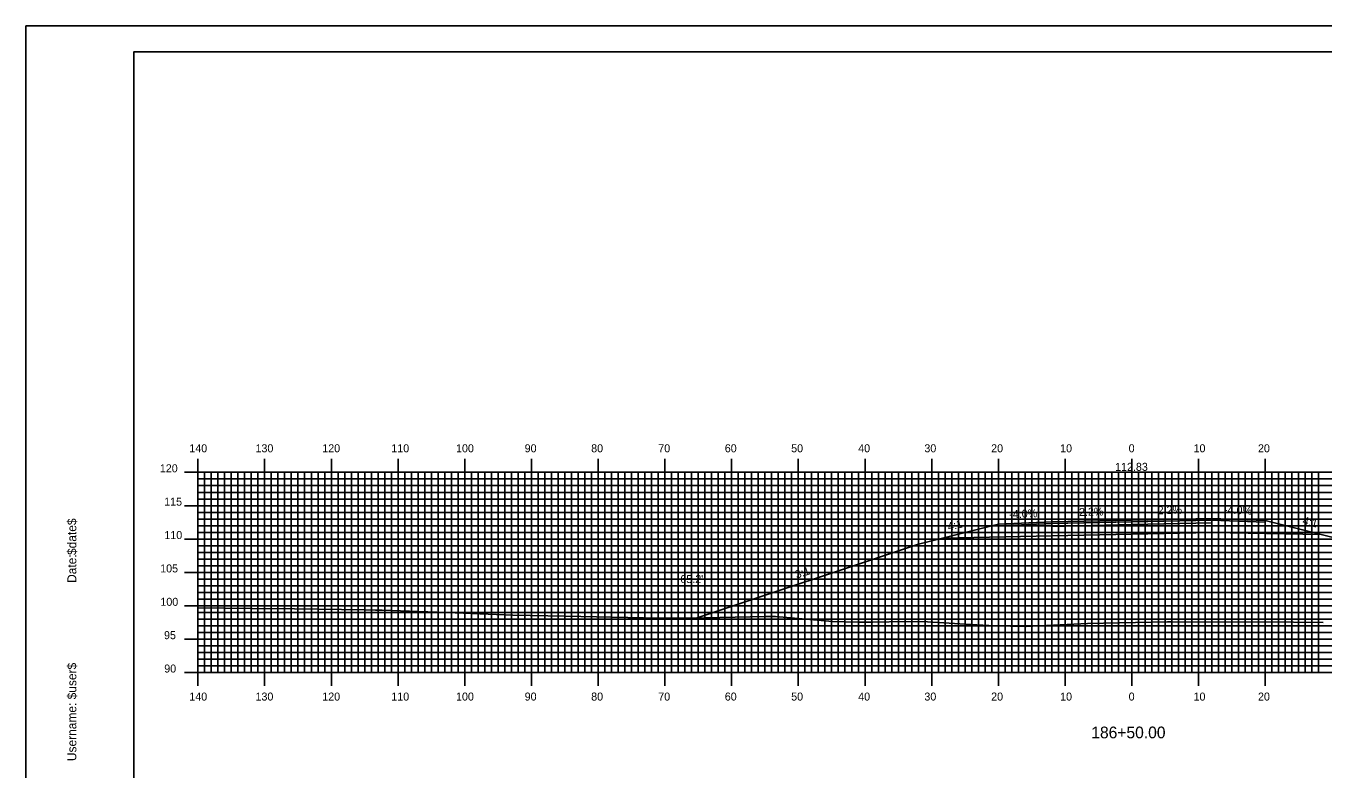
# Model space of a CAD drawing. Extents: x 1787369 to 1787713, y 442591 to 442811.
# Drawn here: x 1787369.3 to 1787563.8, y 442699.2 to 442810.5 of the extents above; entities that cross this region are included whole.
import ezdxf

# ---------------------------------------------------------------- set-up
doc = ezdxf.new("R2010")
doc.units = 0
for name, color, linetype in [('ANNOTATION', 7, 'Continuous'), ('BORDER', 7, 'Continuous'), ('D_Roadway_Centerline', 7, 'Continuous'), ('D_Roadway_Centerline_Text', 7, 'Continuous'), ('D_Roadway_Edge_Shoulder', 7, 'Continuous'), ('D_Roadway_Edge_TW', 7, 'Continuous'), ('D_Roadway_Pavement', 7, 'Continuous'), ('D_Roadway_SlopeLines', 7, 'Continuous'), ('D_Roadway_SubGrade', 7, 'Continuous'), ('D_Text_Standard', 7, 'Continuous'), ('H_V ANNOTATION', 7, 'Continuous'), ('MAJOR', 7, 'Continuous'), ('MINOR', 7, 'Continuous'), ('PLOT BOUNDARY', 7, 'Continuous'), ('S_Roadway_Centerline', 7, 'Continuous')]:
    doc.layers.add(name, color=color, linetype=linetype)

msp = doc.modelspace()

# ---------------------------------------------------------------- linework, layer by layer
at = {"layer": 'BORDER'}
msp.add_lwpolyline([(1787385.5, 442596.67), (1787705.5, 442596.67), (1787705.5, 442806.67), (1787385.5, 442806.67)], close=True, dxfattribs=at)
at = {"layer": 'D_Roadway_Centerline'}
msp.add_lwpolyline([(1787469.92, 442721.85), (1787503.1, 442732.91), (1787506.74, 442733.82), (1787515.1, 442735.91), (1787523.1, 442736.23), (1787535.1, 442736.49), (1787547.1, 442736.76), (1787555.1, 442736.44), (1787563.47, 442734.35), (1787567.1, 442733.44), (1787604.19, 442721.08)], dxfattribs=at)
at = {"layer": 'D_Roadway_Edge_Shoulder'}
for points in [[(1787547.1, 442736.76), (1787555.1, 442736.44), (1787555.1, 442736.19), (1787547.1, 442736.51)], [(1787523.1, 442736.23), (1787515.1, 442735.91), (1787515.1, 442735.66), (1787523.1, 442735.98)]]:
    msp.add_lwpolyline(points, close=True, dxfattribs=at)
at = {"layer": 'D_Roadway_Edge_TW'}
msp.add_lwpolyline([(1787523.1, 442735.98), (1787523.1, 442736.23), (1787535.1, 442736.49), (1787547.1, 442736.76), (1787547.1, 442736.51), (1787535.1, 442736.24)], close=True, dxfattribs=at)
at = {"layer": 'D_Roadway_Pavement'}
msp.add_lwpolyline([(1787523.1, 442735.56), (1787523.1, 442735.98), (1787535.1, 442736.24), (1787547.1, 442736.51), (1787547.1, 442736.09), (1787535.1, 442735.83)], close=True, dxfattribs=at)
at = {"layer": 'D_Roadway_SlopeLines'}
for points in [[(1787515.1, 442735.91), (1787503.1, 442732.91), (1787469.92, 442721.85)], [(1787555.1, 442736.44), (1787567.1, 442733.44), (1787604.19, 442721.08)]]:
    msp.add_lwpolyline(points, dxfattribs=at)
at = {"layer": 'D_Roadway_SubGrade'}
msp.add_lwpolyline([(1787523.1, 442734.15), (1787506.74, 442733.82), (1787515.1, 442735.91), (1787515.1, 442735.66), (1787523.1, 442735.98), (1787535.1, 442736.24), (1787547.1, 442736.51), (1787555.1, 442736.19), (1787555.1, 442736.44), (1787563.47, 442734.35), (1787547.1, 442734.67), (1787535.1, 442734.41)], close=True, dxfattribs=at)
at = {"layer": 'MAJOR'}
for p, q in [((1787395.1, 442745.67), (1787395.1, 442743.67)), ((1787405.1, 442745.67), (1787405.1, 442743.67)), ((1787415.1, 442745.67), (1787415.1, 442743.67)), ((1787425.1, 442745.67), (1787425.1, 442743.67)), ((1787435.1, 442745.67), (1787435.1, 442743.67)), ((1787445.1, 442745.67), (1787445.1, 442743.67)), ((1787455.1, 442745.67), (1787455.1, 442743.67)), ((1787465.1, 442745.67), (1787465.1, 442743.67)), ((1787475.1, 442745.67), (1787475.1, 442743.67)), ((1787485.1, 442745.67), (1787485.1, 442743.67)), ((1787495.1, 442745.67), (1787495.1, 442743.67)), ((1787505.1, 442745.67), (1787505.1, 442743.67)), ((1787515.1, 442745.67), (1787515.1, 442743.67)), ((1787525.1, 442745.67), (1787525.1, 442743.67)), ((1787535.1, 442745.67), (1787535.1, 442743.67)), ((1787545.1, 442745.67), (1787545.1, 442743.67)), ((1787555.1, 442745.67), (1787555.1, 442743.67)), ((1787393.1, 442743.67), (1787395.1, 442743.67)), ((1787395.1, 442743.67), (1787675.1, 442743.67)), ((1787395.1, 442713.67), (1787395.1, 442743.67)), ((1787395.1, 442713.67), (1787395.1, 442743.67)), ((1787395.1, 442743.67), (1787675.1, 442743.67)), ((1787405.1, 442713.67), (1787405.1, 442743.67)), ((1787415.1, 442713.67), (1787415.1, 442743.67)), ((1787425.1, 442713.67), (1787425.1, 442743.67)), ((1787435.1, 442713.67), (1787435.1, 442743.67)), ((1787445.1, 442713.67), (1787445.1, 442743.67)), ((1787455.1, 442713.67), (1787455.1, 442743.67)), ((1787465.1, 442713.67), (1787465.1, 442743.67)), ((1787475.1, 442713.67), (1787475.1, 442743.67)), ((1787485.1, 442713.67), (1787485.1, 442743.67)), ((1787495.1, 442713.67), (1787495.1, 442743.67)), ((1787505.1, 442713.67), (1787505.1, 442743.67)), ((1787515.1, 442713.67), (1787515.1, 442743.67)), ((1787525.1, 442713.67), (1787525.1, 442743.67)), ((1787535.1, 442713.67), (1787535.1, 442743.67)), ((1787545.1, 442713.67), (1787545.1, 442743.67)), ((1787555.1, 442713.67), (1787555.1, 442743.67)), ((1787393.1, 442738.67), (1787395.1, 442738.67)), ((1787395.1, 442738.67), (1787675.1, 442738.67)), ((1787393.1, 442733.67), (1787395.1, 442733.67)), ((1787395.1, 442733.67), (1787675.1, 442733.67)), ((1787393.1, 442728.67), (1787395.1, 442728.67)), ((1787395.1, 442728.67), (1787675.1, 442728.67)), ((1787393.1, 442723.67), (1787395.1, 442723.67)), ((1787395.1, 442723.67), (1787675.1, 442723.67)), ((1787393.1, 442718.67), (1787395.1, 442718.67)), ((1787395.1, 442718.67), (1787675.1, 442718.67)), ((1787393.1, 442713.67), (1787395.1, 442713.67)), ((1787395.1, 442713.67), (1787675.1, 442713.67)), ((1787395.1, 442713.67), (1787675.1, 442713.67)), ((1787395.1, 442711.66), (1787395.1, 442713.67)), ((1787405.1, 442711.66), (1787405.1, 442713.67)), ((1787415.1, 442711.66), (1787415.1, 442713.67)), ((1787425.1, 442711.66), (1787425.1, 442713.67)), ((1787435.1, 442711.66), (1787435.1, 442713.67)), ((1787445.1, 442711.66), (1787445.1, 442713.67)), ((1787455.1, 442711.66), (1787455.1, 442713.67)), ((1787465.1, 442711.66), (1787465.1, 442713.67)), ((1787475.1, 442711.66), (1787475.1, 442713.67)), ((1787485.1, 442711.66), (1787485.1, 442713.67)), ((1787495.1, 442711.66), (1787495.1, 442713.67)), ((1787505.1, 442711.66), (1787505.1, 442713.67)), ((1787515.1, 442711.66), (1787515.1, 442713.67)), ((1787525.1, 442711.66), (1787525.1, 442713.67)), ((1787535.1, 442711.66), (1787535.1, 442713.67)), ((1787545.1, 442711.66), (1787545.1, 442713.67)), ((1787555.1, 442711.66), (1787555.1, 442713.67))]:
    msp.add_line(p, q, dxfattribs=at)
at = {"layer": 'MINOR'}
for p, q in [((1787395.1, 442742.67), (1787675.1, 442742.67)), ((1787395.1, 442742.67), (1787397.11, 442742.67)), ((1787396.1, 442713.67), (1787396.1, 442743.67)), ((1787397.1, 442713.67), (1787397.1, 442743.67)), ((1787398.1, 442713.67), (1787398.1, 442743.67)), ((1787399.1, 442713.67), (1787399.1, 442743.67)), ((1787400.1, 442713.67), (1787400.1, 442743.67)), ((1787401.1, 442713.67), (1787401.1, 442743.67)), ((1787402.1, 442713.67), (1787402.1, 442743.67)), ((1787403.1, 442713.67), (1787403.1, 442743.67)), ((1787404.1, 442713.67), (1787404.1, 442743.67)), ((1787406.1, 442713.67), (1787406.1, 442743.67)), ((1787407.1, 442713.67), (1787407.1, 442743.67)), ((1787408.1, 442713.67), (1787408.1, 442743.67)), ((1787409.1, 442713.67), (1787409.1, 442743.67)), ((1787410.1, 442713.67), (1787410.1, 442743.67)), ((1787411.1, 442713.67), (1787411.1, 442743.67)), ((1787412.1, 442713.67), (1787412.1, 442743.67)), ((1787413.1, 442713.67), (1787413.1, 442743.67)), ((1787414.1, 442713.67), (1787414.1, 442743.67)), ((1787416.1, 442713.67), (1787416.1, 442743.67)), ((1787417.1, 442713.67), (1787417.1, 442743.67)), ((1787418.1, 442713.67), (1787418.1, 442743.67)), ((1787419.1, 442713.67), (1787419.1, 442743.67)), ((1787420.1, 442713.67), (1787420.1, 442743.67)), ((1787421.1, 442713.67), (1787421.1, 442743.67)), ((1787422.1, 442713.67), (1787422.1, 442743.67)), ((1787423.1, 442713.67), (1787423.1, 442743.67)), ((1787424.1, 442713.67), (1787424.1, 442743.67)), ((1787426.1, 442713.67), (1787426.1, 442743.67)), ((1787427.1, 442713.67), (1787427.1, 442743.67)), ((1787428.1, 442713.67), (1787428.1, 442743.67)), ((1787429.1, 442713.67), (1787429.1, 442743.67)), ((1787430.1, 442713.67), (1787430.1, 442743.67)), ((1787431.1, 442713.67), (1787431.1, 442743.67)), ((1787432.1, 442713.67), (1787432.1, 442743.67)), ((1787433.1, 442713.67), (1787433.1, 442743.67)), ((1787434.1, 442713.67), (1787434.1, 442743.67)), ((1787436.1, 442713.67), (1787436.1, 442743.67)), ((1787437.1, 442713.67), (1787437.1, 442743.67)), ((1787438.1, 442713.67), (1787438.1, 442743.67)), ((1787439.1, 442713.67), (1787439.1, 442743.67)), ((1787440.1, 442713.67), (1787440.1, 442743.67)), ((1787441.1, 442713.67), (1787441.1, 442743.67)), ((1787442.1, 442713.67), (1787442.1, 442743.67)), ((1787443.1, 442713.67), (1787443.1, 442743.67)), ((1787444.1, 442713.67), (1787444.1, 442743.67)), ((1787446.1, 442713.67), (1787446.1, 442743.67)), ((1787447.1, 442713.67), (1787447.1, 442743.67)), ((1787448.1, 442713.67), (1787448.1, 442743.67)), ((1787449.1, 442713.67), (1787449.1, 442743.67)), ((1787450.1, 442713.67), (1787450.1, 442743.67)), ((1787451.1, 442713.67), (1787451.1, 442743.67)), ((1787452.1, 442713.67), (1787452.1, 442743.67)), ((1787453.1, 442713.67), (1787453.1, 442743.67)), ((1787454.1, 442713.67), (1787454.1, 442743.67)), ((1787456.1, 442713.67), (1787456.1, 442743.67)), ((1787457.1, 442713.67), (1787457.1, 442743.67)), ((1787458.1, 442713.67), (1787458.1, 442743.67)), ((1787459.1, 442713.67), (1787459.1, 442743.67)), ((1787460.1, 442713.67), (1787460.1, 442743.67)), ((1787461.1, 442713.67), (1787461.1, 442743.67)), ((1787462.1, 442713.67), (1787462.1, 442743.67)), ((1787463.1, 442713.67), (1787463.1, 442743.67)), ((1787464.1, 442713.67), (1787464.1, 442743.67)), ((1787466.1, 442713.67), (1787466.1, 442743.67)), ((1787467.1, 442713.67), (1787467.1, 442743.67)), ((1787468.1, 442713.67), (1787468.1, 442743.67)), ((1787469.1, 442713.67), (1787469.1, 442743.67)), ((1787470.1, 442713.67), (1787470.1, 442743.67)), ((1787471.1, 442713.67), (1787471.1, 442743.67)), ((1787472.1, 442713.67), (1787472.1, 442743.67)), ((1787473.1, 442713.67), (1787473.1, 442743.67)), ((1787474.1, 442713.67), (1787474.1, 442743.67)), ((1787476.1, 442713.67), (1787476.1, 442743.67)), ((1787477.1, 442713.67), (1787477.1, 442743.67)), ((1787478.1, 442713.67), (1787478.1, 442743.67)), ((1787479.1, 442713.67), (1787479.1, 442743.67)), ((1787480.1, 442713.67), (1787480.1, 442743.67)), ((1787481.1, 442713.67), (1787481.1, 442743.67)), ((1787482.1, 442713.67), (1787482.1, 442743.67)), ((1787483.1, 442713.67), (1787483.1, 442743.67)), ((1787484.1, 442713.67), (1787484.1, 442743.67)), ((1787486.1, 442713.67), (1787486.1, 442743.67)), ((1787487.1, 442713.67), (1787487.1, 442743.67)), ((1787488.1, 442713.67), (1787488.1, 442743.67)), ((1787489.1, 442713.67), (1787489.1, 442743.67)), ((1787490.1, 442713.67), (1787490.1, 442743.67)), ((1787491.1, 442713.67), (1787491.1, 442743.67)), ((1787492.1, 442713.67), (1787492.1, 442743.67)), ((1787493.1, 442713.67), (1787493.1, 442743.67)), ((1787494.1, 442713.67), (1787494.1, 442743.67)), ((1787496.1, 442713.67), (1787496.1, 442743.67)), ((1787497.1, 442713.67), (1787497.1, 442743.67)), ((1787498.1, 442713.67), (1787498.1, 442743.67)), ((1787499.1, 442713.67), (1787499.1, 442743.67)), ((1787500.1, 442713.67), (1787500.1, 442743.67)), ((1787501.1, 442713.67), (1787501.1, 442743.67)), ((1787502.1, 442713.67), (1787502.1, 442743.67)), ((1787503.1, 442713.67), (1787503.1, 442743.67)), ((1787504.1, 442713.67), (1787504.1, 442743.67)), ((1787506.1, 442713.67), (1787506.1, 442743.67)), ((1787507.1, 442713.67), (1787507.1, 442743.67)), ((1787508.1, 442713.67), (1787508.1, 442743.67)), ((1787509.1, 442713.67), (1787509.1, 442743.67)), ((1787510.1, 442713.67), (1787510.1, 442743.67)), ((1787511.1, 442713.67), (1787511.1, 442743.67)), ((1787512.1, 442713.67), (1787512.1, 442743.67)), ((1787513.1, 442713.67), (1787513.1, 442743.67)), ((1787514.1, 442713.67), (1787514.1, 442743.67)), ((1787516.1, 442713.67), (1787516.1, 442743.67)), ((1787517.1, 442713.67), (1787517.1, 442743.67)), ((1787518.1, 442713.67), (1787518.1, 442743.67)), ((1787519.1, 442713.67), (1787519.1, 442743.67)), ((1787520.1, 442713.67), (1787520.1, 442743.67)), ((1787521.1, 442713.67), (1787521.1, 442743.67)), ((1787522.1, 442713.67), (1787522.1, 442743.67)), ((1787523.1, 442713.67), (1787523.1, 442743.67)), ((1787524.1, 442713.67), (1787524.1, 442743.67)), ((1787526.1, 442713.67), (1787526.1, 442743.67)), ((1787527.1, 442713.67), (1787527.1, 442743.67)), ((1787528.1, 442713.67), (1787528.1, 442743.67)), ((1787529.1, 442713.67), (1787529.1, 442743.67)), ((1787530.1, 442713.67), (1787530.1, 442743.67)), ((1787531.1, 442713.67), (1787531.1, 442743.67)), ((1787532.1, 442713.67), (1787532.1, 442743.67)), ((1787533.1, 442713.67), (1787533.1, 442743.67)), ((1787534.1, 442713.67), (1787534.1, 442743.67)), ((1787536.1, 442713.67), (1787536.1, 442743.67)), ((1787537.1, 442713.67), (1787537.1, 442743.67)), ((1787538.1, 442713.67), (1787538.1, 442743.67)), ((1787539.1, 442713.67), (1787539.1, 442743.67)), ((1787540.1, 442713.67), (1787540.1, 442743.67)), ((1787541.1, 442713.67), (1787541.1, 442743.67)), ((1787542.1, 442713.67), (1787542.1, 442743.67)), ((1787543.1, 442713.67), (1787543.1, 442743.67)), ((1787544.1, 442713.67), (1787544.1, 442743.67)), ((1787546.1, 442713.67), (1787546.1, 442743.67)), ((1787547.1, 442713.67), (1787547.1, 442743.67)), ((1787548.1, 442713.67), (1787548.1, 442743.67)), ((1787549.1, 442713.67), (1787549.1, 442743.67)), ((1787550.1, 442713.67), (1787550.1, 442743.67)), ((1787551.1, 442713.67), (1787551.1, 442743.67)), ((1787552.1, 442713.67), (1787552.1, 442743.67)), ((1787553.1, 442713.67), (1787553.1, 442743.67)), ((1787554.1, 442713.67), (1787554.1, 442743.67)), ((1787556.1, 442713.67), (1787556.1, 442743.67)), ((1787557.1, 442713.67), (1787557.1, 442743.67)), ((1787558.1, 442713.67), (1787558.1, 442743.67)), ((1787559.1, 442713.67), (1787559.1, 442743.67)), ((1787560.1, 442713.67), (1787560.1, 442743.67)), ((1787561.1, 442713.67), (1787561.1, 442743.67)), ((1787562.1, 442713.67), (1787562.1, 442743.67)), ((1787563.1, 442713.67), (1787563.1, 442743.67)), ((1787395.1, 442741.67), (1787675.1, 442741.67)), ((1787395.1, 442741.67), (1787397.11, 442741.67)), ((1787395.1, 442740.67), (1787675.1, 442740.67)), ((1787395.1, 442740.67), (1787397.11, 442740.67)), ((1787395.1, 442739.67), (1787675.1, 442739.67)), ((1787395.1, 442739.67), (1787397.11, 442739.67)), ((1787395.1, 442737.67), (1787675.1, 442737.67)), ((1787395.1, 442737.67), (1787397.11, 442737.67)), ((1787395.1, 442736.67), (1787675.1, 442736.67)), ((1787395.1, 442736.67), (1787397.11, 442736.67)), ((1787395.1, 442735.67), (1787675.1, 442735.67)), ((1787395.1, 442735.67), (1787397.11, 442735.67)), ((1787395.1, 442734.67), (1787675.1, 442734.67)), ((1787395.1, 442734.67), (1787397.11, 442734.67)), ((1787395.1, 442732.67), (1787675.1, 442732.67)), ((1787395.1, 442732.67), (1787397.11, 442732.67)), ((1787395.1, 442731.67), (1787675.1, 442731.67)), ((1787395.1, 442731.67), (1787397.11, 442731.67)), ((1787395.1, 442730.67), (1787675.1, 442730.67)), ((1787395.1, 442730.67), (1787397.11, 442730.67)), ((1787395.1, 442729.67), (1787675.1, 442729.67)), ((1787395.1, 442729.67), (1787397.11, 442729.67)), ((1787395.1, 442727.67), (1787675.1, 442727.67)), ((1787395.1, 442727.67), (1787397.11, 442727.67)), ((1787395.1, 442726.67), (1787675.1, 442726.67)), ((1787395.1, 442726.67), (1787397.11, 442726.67)), ((1787395.1, 442725.67), (1787675.1, 442725.67)), ((1787395.1, 442725.67), (1787397.11, 442725.67)), ((1787395.1, 442724.67), (1787675.1, 442724.67)), ((1787395.1, 442724.67), (1787397.11, 442724.67)), ((1787395.1, 442722.67), (1787675.1, 442722.67)), ((1787395.1, 442722.67), (1787397.11, 442722.67)), ((1787395.1, 442721.67), (1787675.1, 442721.67)), ((1787395.1, 442721.67), (1787397.11, 442721.67)), ((1787395.1, 442720.67), (1787675.1, 442720.67)), ((1787395.1, 442720.67), (1787397.11, 442720.67)), ((1787395.1, 442719.67), (1787675.1, 442719.67)), ((1787395.1, 442719.67), (1787397.11, 442719.67)), ((1787395.1, 442717.67), (1787675.1, 442717.67)), ((1787395.1, 442717.67), (1787397.11, 442717.67)), ((1787395.1, 442716.67), (1787675.1, 442716.67)), ((1787395.1, 442716.67), (1787397.11, 442716.67)), ((1787395.1, 442715.67), (1787675.1, 442715.67)), ((1787395.1, 442715.67), (1787397.11, 442715.67)), ((1787395.1, 442714.67), (1787675.1, 442714.67)), ((1787395.1, 442714.67), (1787397.11, 442714.67))]:
    msp.add_line(p, q, dxfattribs=at)
at = {"layer": 'PLOT BOUNDARY'}
msp.add_lwpolyline([(1787369.32, 442590.55), (1787709.32, 442590.55), (1787709.32, 442810.55), (1787369.32, 442810.55)], close=True, dxfattribs=at)
at = {"layer": 'S_Roadway_Centerline'}
msp.add_lwpolyline([(1787395.1, 442723.35), (1787403.24, 442723.27), (1787409.56, 442723.21), (1787420.13, 442723.06), (1787421.71, 442723.03), (1787422.74, 442723.01), (1787433.67, 442722.61), (1787442.33, 442722.29), (1787450.13, 442722.13), (1787457.2, 442721.97), (1787461.9, 442721.88), (1787468.78, 442721.82), (1787480.17, 442722.06), (1787481.1, 442722.07), (1787481.7, 442722.05), (1787490.25, 442721.34), (1787494.17, 442721.21), (1787496.27, 442721.22), (1787501.24, 442721.31), (1787504.47, 442721.25), (1787510.94, 442720.85), (1787514.58, 442720.68), (1787519.27, 442720.55), (1787528.45, 442721.03), (1787540.43, 442721.27), (1787540.67, 442721.27), (1787541.04, 442721.27), (1787559.31, 442721.23), (1787563.78, 442721.19)], dxfattribs=at)

# ---------------------------------------------------------------- texts
at = {"layer": 'ANNOTATION'}
for s, rotation, p in [('2.2%', 1.2603, (1787538.98, 442737.38)), ('-4.0%', 357.7094, (1787548.9, 442737.49)), ('-4.0%', 2.2906, (1787516.74, 442736.78)), ('-2.2%', 1.2603, (1787526.66, 442737.11)), ('4:1', 345.9638, (1787560.61, 442735.92)), ('4:1', 14.0362, (1787507.64, 442734.9)), ('3:1', 18.4348, (1787484.85, 442727.73))]:
    msp.add_text(s, height=1.2, rotation=rotation, dxfattribs=at).set_placement(p)
at = {"layer": 'BORDER'}
for s, p in [('$date$', (1787376.87, 442731.28)), ('Date:', (1787376.87, 442727.1)), ('$user$', (1787376.87, 442709.65)), ('Username:', (1787376.87, 442700.4))]:
    msp.add_text(s, height=1.339, rotation=90, dxfattribs=at).set_placement(p)
at = {"layer": 'D_Roadway_Centerline'}
for s in ['C', 'L']:
    msp.add_text(s, height=0.0146, dxfattribs=at).set_placement((1787535.1, 442736.49))
at = {"layer": 'D_Roadway_Centerline_Text'}
msp.add_text('112.83', height=1.2, dxfattribs=at).set_placement((1787532.59, 442743.89))
at = {"layer": 'D_Text_Standard'}
msp.add_text("65.2'", height=1.2, dxfattribs=at).set_placement((1787467.42, 442727.08))
at = {"layer": 'H_V ANNOTATION'}
for s, height, p in [('140', 1.2, (1787393.81, 442746.67)), ('130', 1.2, (1787403.73, 442746.67)), ('120', 1.2, (1787413.74, 442746.67)), ('110', 1.2, (1787424.09, 442746.67)), ('100', 1.2, (1787433.79, 442746.67)), ('90', 1.2, (1787444.08, 442746.67)), ('80', 1.2, (1787454.05, 442746.67)), ('70', 1.2, (1787464.11, 442746.67)), ('60', 1.2, (1787474.08, 442746.67)), ('50', 1.2, (1787484.03, 442746.67)), ('40', 1.2, (1787494.08, 442746.67)), ('30', 1.2, (1787504, 442746.67)), ('20', 1.2, (1787514.01, 442746.67)), ('10', 1.2, (1787524.35, 442746.67)), ('0', 1.2, (1787534.62, 442746.67)), ('10', 1.2, (1787544.35, 442746.67)), ('20', 1.2, (1787554.01, 442746.67)), ('120', 1.2, (1787389.39, 442743.67)), ('115', 1.2, (1787390.04, 442738.67)), ('110', 1.2, (1787390.07, 442733.67)), ('105', 1.2, (1787389.44, 442728.67)), ('100', 1.2, (1787389.47, 442723.67)), ('95', 1.2, (1787390.02, 442718.67)), ('90', 1.2, (1787390.05, 442713.67)), ('140', 1.2, (1787393.81, 442709.47)), ('130', 1.2, (1787403.73, 442709.47)), ('120', 1.2, (1787413.74, 442709.47)), ('110', 1.2, (1787424.09, 442709.47)), ('100', 1.2, (1787433.79, 442709.47)), ('90', 1.2, (1787444.08, 442709.47)), ('80', 1.2, (1787454.05, 442709.47)), ('70', 1.2, (1787464.11, 442709.47)), ('60', 1.2, (1787474.08, 442709.47)), ('50', 1.2, (1787484.03, 442709.47)), ('40', 1.2, (1787494.08, 442709.47)), ('30', 1.2, (1787504, 442709.47)), ('20', 1.2, (1787514.01, 442709.47)), ('10', 1.2, (1787524.35, 442709.47)), ('0', 1.2, (1787534.62, 442709.47)), ('10', 1.2, (1787544.35, 442709.47)), ('20', 1.2, (1787554.01, 442709.47)), ('186+50.00', 1.75, (1787529.02, 442703.82))]:
    msp.add_text(s, height=height, dxfattribs=at).set_placement(p)
at = {"layer": 'MAJOR'}
msp.add_text('-', height=0.012, dxfattribs=at).set_placement((1787395.1, 442713.67))

doc.saveas('drawing.dxf')
